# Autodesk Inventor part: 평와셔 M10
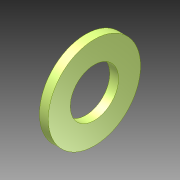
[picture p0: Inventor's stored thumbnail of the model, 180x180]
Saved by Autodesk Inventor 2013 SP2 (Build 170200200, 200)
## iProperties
Created: 2025-04
Part Number: 평와셔 M10
Material: Generic
Document SubType Name: Modeling
Designer: 601
Density: 1 g/cm^3
Author: 601
변환 표준: STEP AP214IS
전처리기: Build: 200, Release: 2013 SP2 Update 6 - Date: Thu 07/17/2014
전송 단위: 밀리미터
불확실성: 0.01
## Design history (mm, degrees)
node "평와셔 M101"
body "Solid1"
node "기준1"
